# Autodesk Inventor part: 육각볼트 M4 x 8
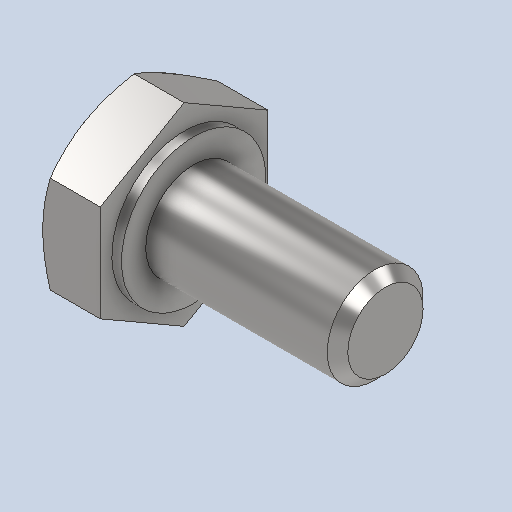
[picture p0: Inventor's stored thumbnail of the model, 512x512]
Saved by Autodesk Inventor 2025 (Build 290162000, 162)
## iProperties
Created: 2024-07
Part Number: 육각볼트 M4 x 8
Material: 강철, 연강
Description: 6각 머리 나사
Document SubType Name: Modeling
Designer: hsj03
Density: 7.86 g/cm^3
Appearance: 기본값
Author: jhkim
Sending System: Autodesk Inventor 2025
Preprocessor: ST-DEVELOPER v20
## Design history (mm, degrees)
feature "Solid1"
node "솔리드1"
